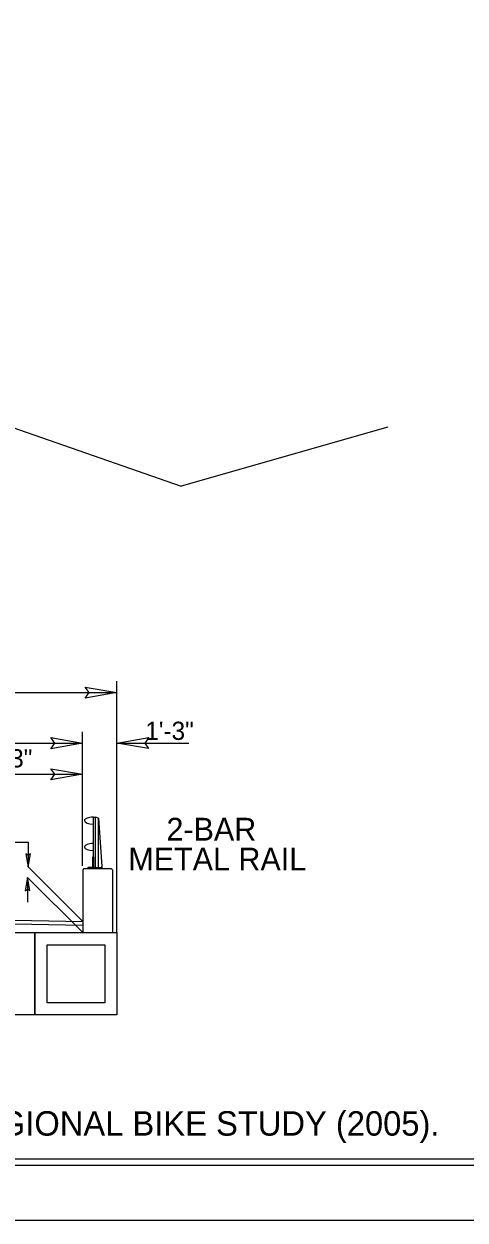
# Model space of a CAD drawing. Extents: x 55823 to 57507, y 47399 to 48499.
# Drawn here: x 56749.5 to 56929.9, y 47399.4 to 47888.6 of the extents above; entities that cross this region are included whole.
import ezdxf

# ---------------------------------------------------------------- set-up
doc = ezdxf.new("R2010")
doc.units = 0
for name, color, linetype in [('Old_Level_1', 7, 'Continuous'), ('Old_Level_11', 7, 'Continuous'), ('Old_Level_28', 7, 'Continuous'), ('Sheet Plot Border Inside CELL', 7, 'Continuous'), ('Sheet Plot Border Outside CELL', 7, 'Continuous'), ('Sheet Typical CELL', 7, 'Continuous'), ('Typical Bridge Rail Two Bar CELL', 7, 'Continuous'), ('Typical Terminator CELL', 7, 'Continuous'), ('Typical Text General CELL', 7, 'Continuous')]:
    doc.layers.add(name, color=color, linetype=linetype)

msp = doc.modelspace()

# ---------------------------------------------------------------- linework, layer by layer
at = {"layer": 'Old_Level_1'}
msp.add_line((56735.67, 47726.67), (56813.86, 47699.47), dxfattribs=at)
msp.add_lwpolyline([(56898.3, 47723.64), (56813.86, 47699.47)], dxfattribs=at)
at = {"layer": 'Old_Level_11'}
for p, q in [((56417.91, 47615.15), (56787.52, 47615.15)), ((56431.58, 47594.45), (56773.49, 47594.45)), ((56787.52, 47594.45), (56816.88, 47594.45))]:
    msp.add_line(p, q, dxfattribs=at)
at = {"layer": 'Old_Level_28'}
for p, q in [((56787.52, 47516.98), (56787.52, 47619.77)), ((56773.49, 47544.27), (56773.49, 47599.06)), ((56716.74, 47581.71), (56773.49, 47581.71)), ((56602.71, 47524.95), (56773.52, 47521.48)), ((56602.68, 47523.45), (56773.49, 47519.98))]:
    msp.add_line(p, q, dxfattribs=at)
for points in [[(56774.58, 47617.38), (56787.52, 47615.15), (56774.51, 47612.85), (56776.16, 47615.15)], [(56760.55, 47596.68), (56773.49, 47594.45), (56760.48, 47592.15), (56762.13, 47594.45)], [(56800.46, 47592.22), (56787.52, 47594.45), (56800.53, 47596.75), (56798.87, 47594.45)], [(56760.55, 47583.94), (56773.49, 47581.71), (56760.48, 47579.41), (56762.13, 47581.71)], [(56720.32, 47516.98), (56753.92, 47516.98), (56753.92, 47483.28), (56720.32, 47483.28)], [(56753.92, 47516.98), (56787.52, 47516.98), (56787.52, 47483.28), (56753.92, 47483.28)], [(56782.52, 47511.98), (56782.52, 47488.28), (56758.92, 47488.28), (56758.92, 47511.98)]]:
    msp.add_lwpolyline(points, close=True, dxfattribs=at)
at = {"layer": 'Sheet Plot Border Inside CELL'}
msp.add_lwpolyline([(57502.66, 48476.93), (55836.16, 48476.93), (55836.16, 47421.83), (57502.66, 47421.83)], close=True, dxfattribs=at)
at = {"layer": 'Sheet Plot Border Outside CELL'}
msp.add_lwpolyline([(57507.16, 48499.38), (55823.16, 48499.38), (55823.16, 47399.38), (57507.16, 47399.38)], close=True, dxfattribs=at)
at = {"layer": 'Sheet Typical CELL'}
msp.add_lwpolyline([(57490.16, 48474.38), (55990.16, 48474.38), (55990.16, 47424.38), (57490.16, 47424.38)], close=True, dxfattribs=at)
at = {"layer": 'Typical Bridge Rail Two Bar CELL'}
for p, q in [((56777.88, 47564.2), (56778.71, 47564.2)), ((56777.88, 47543.59), (56777.88, 47564.2)), ((56779.96, 47563.79), (56778.71, 47564.2)), ((56778.71, 47543.59), (56778.71, 47564.2)), ((56779.96, 47543.59), (56779.96, 47563.79)), ((56779.96, 47563.79), (56781.39, 47544)), ((56779.96, 47554.33), (56780, 47554.33)), ((56781.39, 47543.59), (56781.39, 47544)), ((56774.05, 47543.17), (56773.52, 47542.64)), ((56773.52, 47542.64), (56773.52, 47516.98)), ((56774.05, 47543.17), (56785.22, 47543.17)), ((56785.76, 47542.64), (56785.22, 47543.17)), ((56785.76, 47542.64), (56785.76, 47516.98))]:
    msp.add_line(p, q, dxfattribs=at)
msp.add_lwpolyline([(56775.77, 47543.17), (56775.77, 47543.69), (56777.68, 47543.69), (56777.68, 47547.92), (56777.88, 47547.92), (56777.88, 47543.59), (56781.3, 47543.59), (56781.3, 47543.89), (56781.39, 47543.89), (56781.39, 47543.17), (56779.75, 47543.17), (56778.09, 47543.17), (56775.77, 47543.17)], dxfattribs=at)
for centre, start_param, end_param in [((56777.89, 47562.74), 4.712404, 6.283584), ((56777.89, 47562.74), 0.000398, 1.570782), ((56777.89, 47551.93), 4.712404, 6.283584), ((56777.89, 47551.93), 0.000398, 1.570782)]:
    msp.add_ellipse(centre, major_axis=(-3.66, 0), ratio=0.39036, start_param=start_param, end_param=end_param, dxfattribs=at)
at = {"layer": 'Typical Terminator CELL'}
for points in [[(56750.27, 47549.19), (56751.2, 47543.8), (56752.16, 47549.22), (56751.2, 47548.53)], [(56751.92, 47534.12), (56750.99, 47539.51), (56750.03, 47534.09), (56750.99, 47534.78)]]:
    msp.add_lwpolyline(points, close=True, dxfattribs=at)
at = {"layer": 'Typical Text General CELL'}
for p, q in [((56683.84, 47553.92), (56751.2, 47553.92)), ((56751.2, 47553.92), (56751.2, 47543.8)), ((56773.52, 47521.48), (56751.2, 47543.8)), ((56773.52, 47516.98), (56750.99, 47539.51)), ((56750.99, 47539.51), (56750.99, 47529.39))]:
    msp.add_line(p, q, dxfattribs=at)

# ---------------------------------------------------------------- texts
at = {"layer": 'Old_Level_28'}
for s, height, p in [('1\'-3"', 7.447, (56799.12, 47595.75)), ('4\'-3"', 7.447, (56733.1, 47584.51)), ('SR 1767 IS IDENTIFIED AS A BIKE ROUTE IN THE PIEDMONT TRIAD REGIONAL BIKE STUDY (2005).', 10, (56286.37, 47433.91))]:
    msp.add_text(s, height=height, dxfattribs=at).set_placement(p)
at = {"layer": 'Typical Text General CELL'}
for s, p in [('2-BAR', (56807.79, 47554.57)), ('METAL RAIL', (56792.18, 47542.35))]:
    msp.add_text(s, height=9.326, rotation=360, dxfattribs=at).set_placement(p)

doc.saveas('drawing.dxf')
